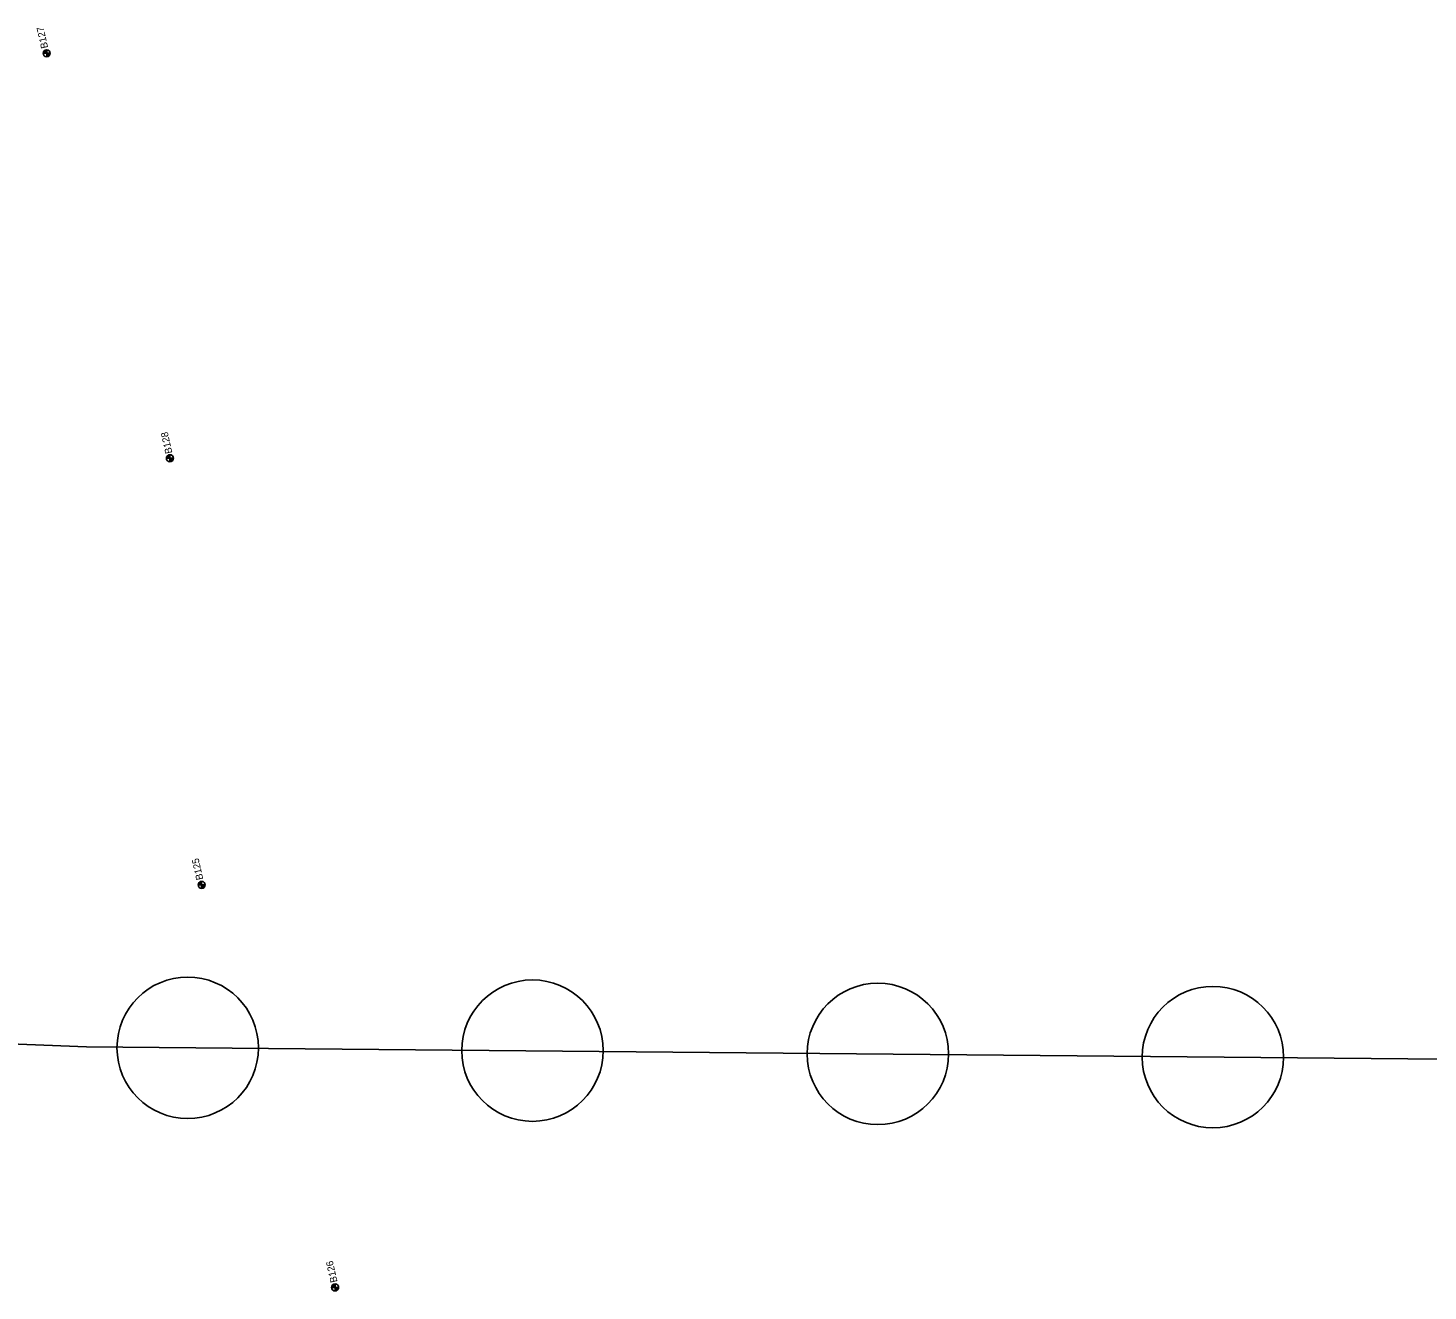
# Model space of a CAD drawing. Extents: x 335726 to 369746, y 119154 to 200788.
# Drawn here: x 356118 to 358105, y 197719 to 199512 of the extents above; entities that cross this region are included whole.
import ezdxf

# ---------------------------------------------------------------- set-up
doc = ezdxf.new("R2010")
doc.units = 0
for name, color, linetype in [('CE-TOPO-CONC-SLAB', 7, 'Continuous'), ('E_SOIL_BORE1 [KAPUR_CADDS_LEVELS]', 7, 'Continuous'), ('E_SOIL_BORE2 [KAPUR_CADDS_LEVELS]', 7, 'Continuous'), ('Level 2', 7, 'Continuous'), ('P_MARK', 7, 'Continuous')]:
    doc.layers.add(name, color=color, linetype=linetype)

msp = doc.modelspace()

# ---------------------------------------------------------------- linework, layer by layer
at = {"layer": 'CE-TOPO-CONC-SLAB'}
for centre in [(356344.6, 198064), (356834, 198060), (357324.3, 198055.4), (357799.9, 198050.8)]:
    msp.add_circle(centre, 100.4, dxfattribs=at)
at = {"layer": 'Level 2'}
msp.add_lwpolyline([(345917.9, 198083.4), (346201.6, 198080.8), (348578.3, 198059.3), (352881.5, 198037), (353407, 198048.9), (354475.4, 198147.6), (354867.1, 198110.7), (355100.6, 198108.6), (356201, 198065.3), (356459.5, 198063), (358911.3, 198040.8), (361421.8, 198068), (361697, 198065.5), (361725, 198066)], dxfattribs=at)
at = {"layer": 'P_MARK'}
for p, q in [((356139.4, 199476.4), (356149.4, 199476.4)), ((356144.4, 199481.4), (356144.4, 199471.4)), ((356314.3, 198901.3), (356324.3, 198901.3)), ((356319.3, 198906.3), (356319.3, 198896.3)), ((356364.4, 198300.4), (356364.4, 198290.4)), ((356359.4, 198295.4), (356369.4, 198295.4)), ((356548.9, 197723.7), (356558.9, 197723.7)), ((356553.9, 197728.7), (356553.9, 197718.7))]:
    msp.add_line(p, q, dxfattribs=at)
for centre in [(356144.4, 199476.4), (356319.3, 198901.3), (356364.4, 198295.4), (356553.9, 197723.7)]:
    msp.add_circle(centre, 5, dxfattribs=at)
for centre, radius, start, end in [((356144.4, 199476.4), 4.5, 89.9869, 179.9869), ((356144.4, 199476.4), 4, 89.9869, 179.9869), ((356144.4, 199476.4), 3.5, 89.9869, 179.9869), ((356144.4, 199476.4), 3, 89.9869, 179.9869), ((356144.4, 199476.4), 2.5, 89.9869, 179.9869), ((356144.4, 199476.4), 2, 89.9869, 179.9869), ((356144.4, 199476.4), 1.5, 89.9869, 179.9869), ((356144.4, 199476.4), 1, 89.9869, 179.9869), ((356144.4, 199476.4), 0.5, 89.9869, 179.9869), ((356144.4, 199476.4), 4.5, 269.9869, 359.9869), ((356144.4, 199476.4), 4, 269.9869, 359.9869), ((356144.4, 199476.4), 3.5, 269.9869, 359.9869), ((356144.4, 199476.4), 3, 269.9869, 359.9869), ((356144.4, 199476.4), 2.5, 269.9869, 359.9869), ((356144.4, 199476.4), 2, 269.9869, 359.9869), ((356144.4, 199476.4), 1.5, 269.9869, 359.9869), ((356144.4, 199476.4), 1, 269.9869, 359.9869), ((356144.4, 199476.4), 0.5, 269.9869, 359.9869), ((356319.3, 198901.3), 4.5, 89.9869, 179.9869), ((356319.3, 198901.3), 4, 89.9869, 179.9869), ((356319.3, 198901.3), 3.5, 89.9869, 179.9869), ((356319.3, 198901.3), 3, 89.9869, 179.9869), ((356319.3, 198901.3), 2.5, 89.9869, 179.9869), ((356319.3, 198901.3), 2, 89.9869, 179.9869), ((356319.3, 198901.3), 1.5, 89.9869, 179.9869), ((356319.3, 198901.3), 1, 89.9869, 179.9869), ((356319.3, 198901.3), 0.5, 89.9869, 179.9869), ((356319.3, 198901.3), 4.5, 269.9869, 359.9869), ((356319.3, 198901.3), 4, 269.9869, 359.9869), ((356319.3, 198901.3), 3.5, 269.9869, 359.9869), ((356319.3, 198901.3), 3, 269.9869, 359.9869), ((356319.3, 198901.3), 2.5, 269.9869, 359.9869), ((356319.3, 198901.3), 2, 269.9869, 359.9869), ((356319.3, 198901.3), 1.5, 269.9869, 359.9869), ((356319.3, 198901.3), 1, 269.9869, 359.9869), ((356319.3, 198901.3), 0.5, 269.9869, 359.9869), ((356364.4, 198295.4), 4.5, 89.9869, 179.9869), ((356364.4, 198295.4), 4, 89.9869, 179.9869), ((356364.4, 198295.4), 3.5, 89.9869, 179.9869), ((356364.4, 198295.4), 3, 89.9869, 179.9869), ((356364.4, 198295.4), 2.5, 89.9869, 179.9869), ((356364.4, 198295.4), 2, 89.9869, 179.9869), ((356364.4, 198295.4), 1.5, 89.9869, 179.9869), ((356364.4, 198295.4), 1, 89.9869, 179.9869), ((356364.4, 198295.4), 0.5, 89.9869, 179.9869), ((356364.4, 198295.4), 4.5, 269.9869, 359.9869), ((356364.4, 198295.4), 4, 269.9869, 359.9869), ((356364.4, 198295.4), 3.5, 269.9869, 359.9869), ((356364.4, 198295.4), 3, 269.9869, 359.9869), ((356364.4, 198295.4), 2.5, 269.9869, 359.9869), ((356364.4, 198295.4), 2, 269.9869, 359.9869), ((356364.4, 198295.4), 1.5, 269.9869, 359.9869), ((356364.4, 198295.4), 1, 269.9869, 359.9869), ((356364.4, 198295.4), 0.5, 269.9869, 359.9869), ((356553.9, 197723.7), 4.5, 89.9869, 179.9869), ((356553.9, 197723.7), 4, 89.9869, 179.9869), ((356553.9, 197723.7), 3.5, 89.9869, 179.9869), ((356553.9, 197723.7), 3, 89.9869, 179.9869), ((356553.9, 197723.7), 2.5, 89.9869, 179.9869), ((356553.9, 197723.7), 2, 89.9869, 179.9869), ((356553.9, 197723.7), 1.5, 89.9869, 179.9869), ((356553.9, 197723.7), 1, 89.9869, 179.9869), ((356553.9, 197723.7), 0.5, 89.9869, 179.9869), ((356553.9, 197723.7), 4.5, 269.9869, 359.9869), ((356553.9, 197723.7), 4, 269.9869, 359.9869), ((356553.9, 197723.7), 3.5, 269.9869, 359.9869), ((356553.9, 197723.7), 3, 269.9869, 359.9869), ((356553.9, 197723.7), 2.5, 269.9869, 359.9869), ((356553.9, 197723.7), 2, 269.9869, 359.9869), ((356553.9, 197723.7), 1.5, 269.9869, 359.9869), ((356553.9, 197723.7), 1, 269.9869, 359.9869), ((356553.9, 197723.7), 0.5, 269.9869, 359.9869)]:
    msp.add_arc(centre, radius, start, end, dxfattribs=at)

# ---------------------------------------------------------------- texts
at = {"layer": 'E_SOIL_BORE1 [KAPUR_CADDS_LEVELS]'}
for s, p in [('B127', (356146.5, 199484.4)), ('B128', (356322.9, 198908.9)), ('B125', (356366.8, 198303.5))]:
    msp.add_text(s, height=10, rotation=102.6348, dxfattribs=at).set_placement(p)
at = {"layer": 'E_SOIL_BORE2 [KAPUR_CADDS_LEVELS]'}
msp.add_text('B126', height=10, rotation=102.6348, dxfattribs=at).set_placement((356557.3, 197731.8))

doc.saveas('drawing.dxf')
